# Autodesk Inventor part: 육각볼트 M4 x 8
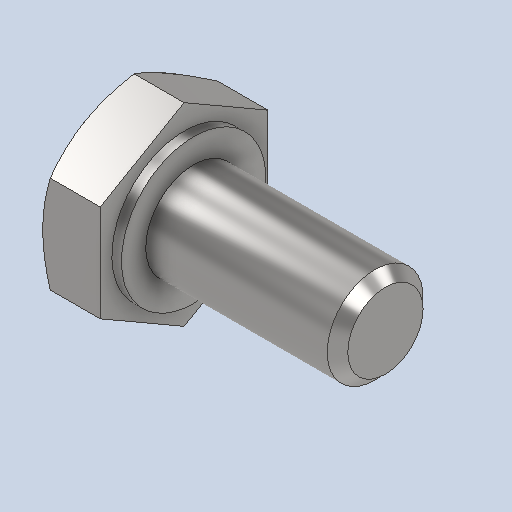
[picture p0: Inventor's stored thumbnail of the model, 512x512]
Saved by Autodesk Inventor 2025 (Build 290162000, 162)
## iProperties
Created: 2024-07
Part Number: 육각볼트 M4 x 8
Material: 강철, 연강
Description: 6각 머리 나사
Document SubType Name: Modeling
Designer: 학생
Density: 7.86 g/cm^3
Appearance: 기본값
Author: jhkim
Sending System: Autodesk Inventor 2025
Preprocessor: ST-DEVELOPER v20
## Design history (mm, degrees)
feature "Solid1"
node "솔리드1"
